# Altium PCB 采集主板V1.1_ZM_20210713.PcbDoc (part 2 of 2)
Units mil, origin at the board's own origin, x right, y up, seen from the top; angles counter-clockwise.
Board outline 5118.11 x 2559.06 mil, 4 copper layers (Top Layer, GND, Power, Bottom Layer), stack 30.635 mil thick; 191 components, 119 nets, 558 pads, 477 vias.
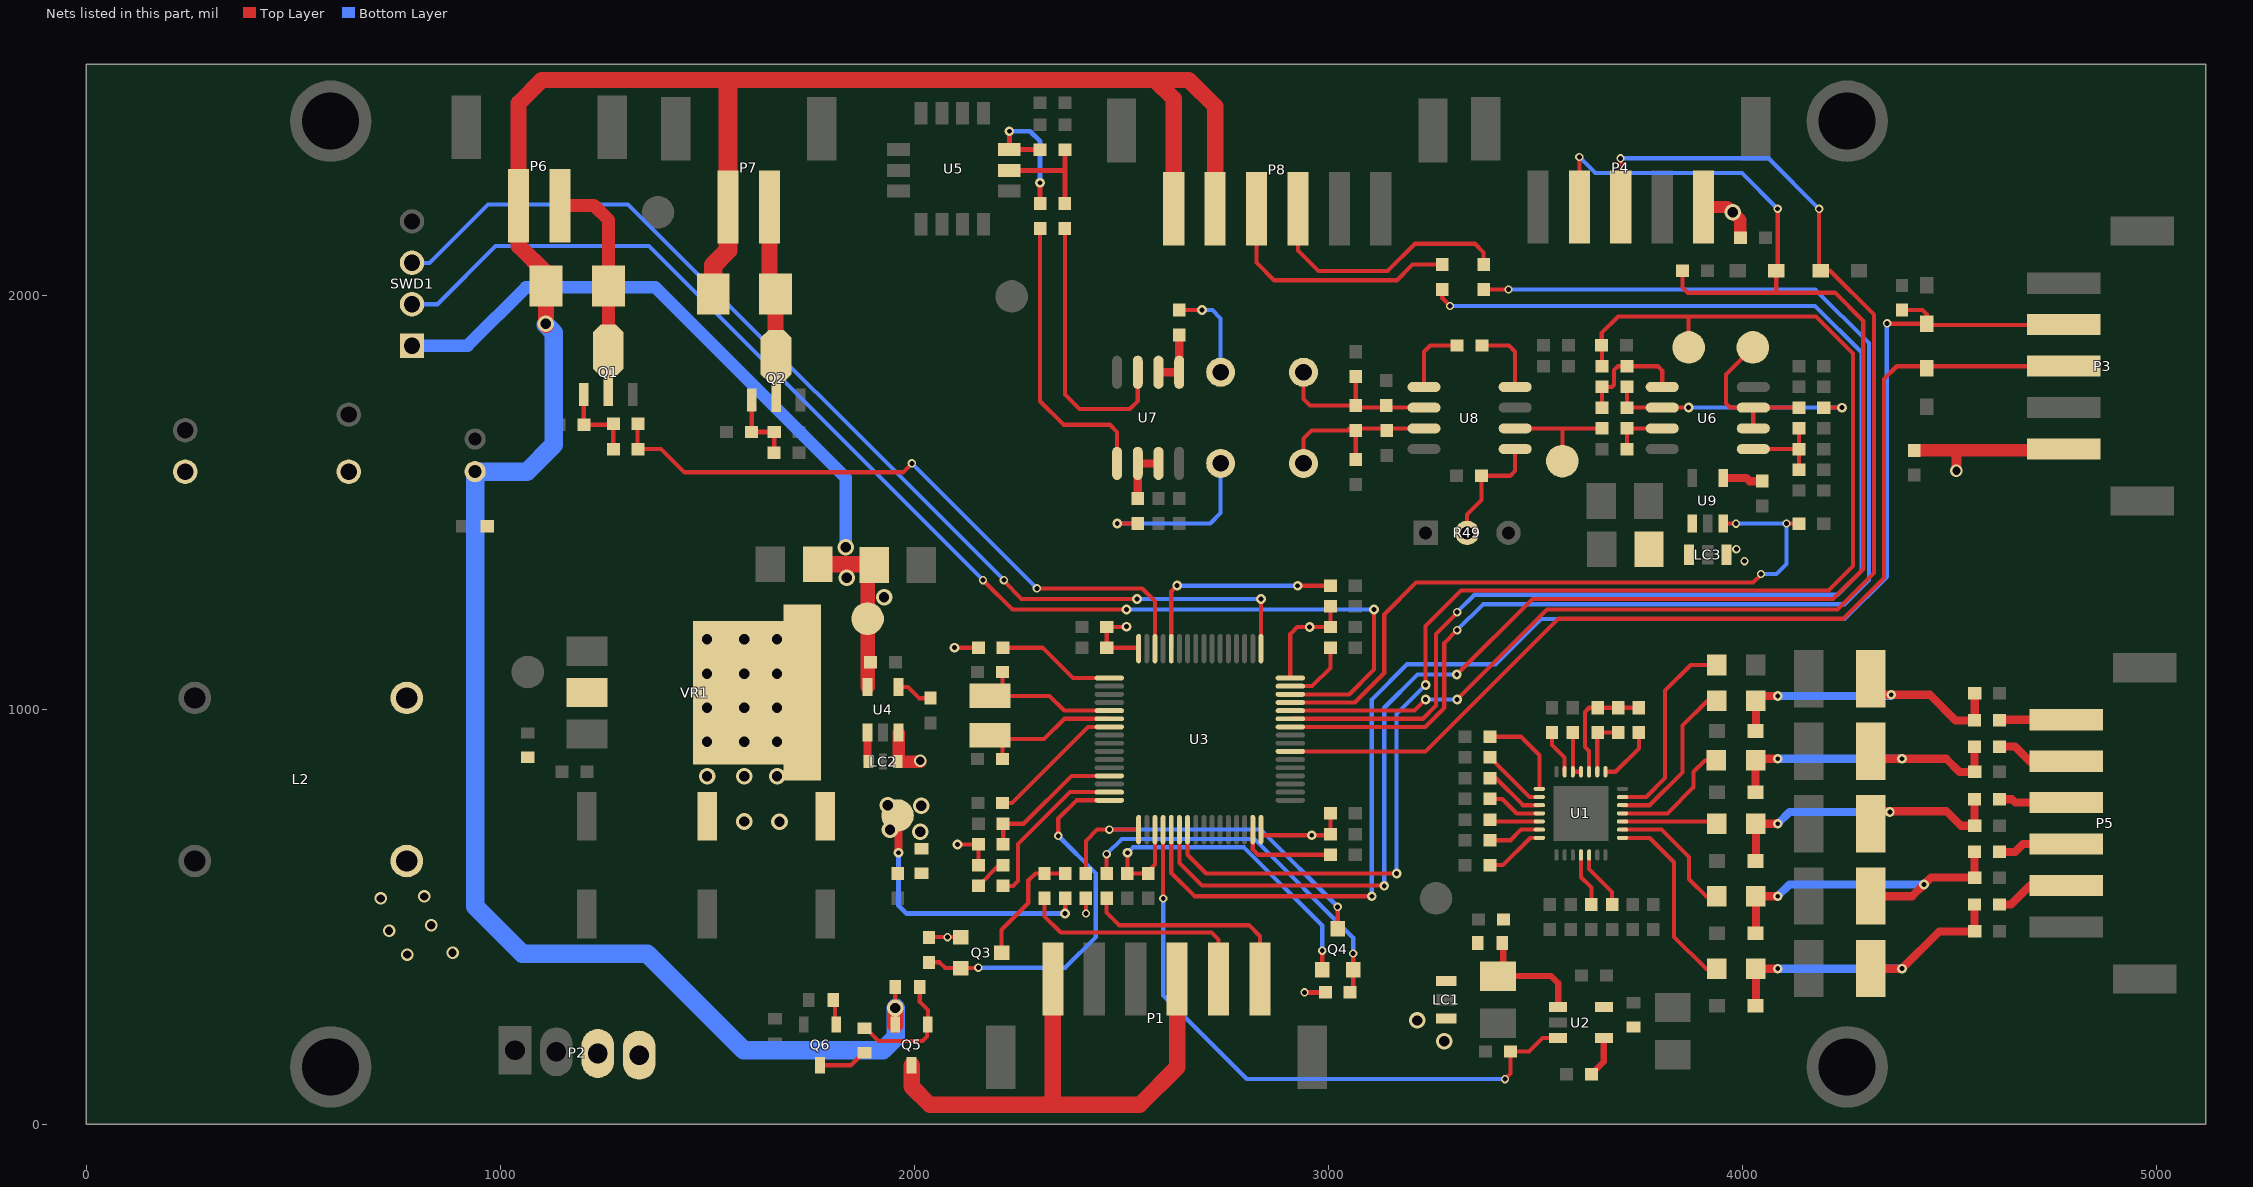
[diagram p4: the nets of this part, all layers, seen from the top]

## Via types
v1: diameter 30, hole 20, Top Layer to Bottom Layer, tented both sides, 321 vias
v2: diameter 40, hole 25, Top Layer to Bottom Layer, tented both sides, 61 vias
v3: diameter 23.62, hole 11.81, Top Layer to Bottom Layer, tented both sides, 49 vias
v4: diameter 20, hole 12, Top Layer to Bottom Layer, tented both sides, 45 vias
v5: diameter 20, hole 12, Top Layer to Bottom Layer, 1 vias

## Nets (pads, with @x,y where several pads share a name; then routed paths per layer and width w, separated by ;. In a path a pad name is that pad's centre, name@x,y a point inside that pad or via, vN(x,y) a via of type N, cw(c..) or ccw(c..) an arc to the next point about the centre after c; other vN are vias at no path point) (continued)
NetC3_1: C3.1 C4.1 C5.2 FB3.1 VR1.2 | length 2.7
  Top Layer w39.37: C4.1@1784.25,743.11 C4.1@1786.14,745
  other v2: 1589.25,730.32 1674.25,730 1499.25,840 1589.25,840 1668.31,840 1499.25,922.5 1589.25,922.5 1668.31,922.5 1499.25,1005 1589.25,1005 1668.31,1005 1499.25,1087.5 1589.25,1087.5 1668.31,1087.5 1499.25,1170 1589.25,1170 1668.31,1170
NetC6_2: C6.2 U1.26 | length 142.5
  Top Layer w10: U1.26@3628.94,649.61 3628.94,615.32 3684.25,560 C6.2@3684.25,530
NetC7_1: C7.1 R22.1 U1.9 | length 144
  Top Layer w10: U1.9@3648.62,850.39 C7.1@3648.62,944.37 ; C7.1@3649.25,945 R22.1@3699.25,945
NetC7_2: C7.2 R20.2 R22.2 U1.10 | length 282.8
  Top Layer w10: U1.10@3628.94,850.39 3628.94,900.32 3619.25,910 3619.25,995 3629.25,1005 C7.2@3649.25,1005 R22.2@3699.25,1005 R20.2@3749.25,1005
NetC8_2: C8.2 U1.11 U1.12 | length 114.4
  Top Layer w10: C8.2@3589.25,945 3589.57,944.68 U1.12@3589.57,850.39 U1.11@3609.25,850.39
NetC13_1: C13.1 C66.1 FB1.2 U2.1 | length 301.9
  Top Layer w15: FB1.2@3421.78,444.17 3421.78,369.61 C13.1@3409.25,357.09 3537.17,357.09 3554.13,340.12 U2.1@3554.13,282.4
NetC16_1: C16.1 Q1.1 R27.1 R29.1 | length 206.4
  Top Layer w10: Q1.1@1201.65,1761.48 R29.1@1201.65,1688.43 1270.63,1688.43 R27.1@1272.87,1690.68 C16.1@1272.87,1629.53
NetC17_1: C17.1 Q2.1 R28.1 R30.1 | length 183
  Top Layer w11.81: Q2.1@1607.06,1747.75 1607.06,1671.67 R30.1@1606.11,1670.73 R28.1@1661.5,1670.73 1661.5,1621.12 C17.1@1661.11,1620.73
NetC20_2: C20.2 U3.31 | length 240.7
  Top Layer w10: U3.31@2816.93,710.63 2816.93,662.32 2829.25,650 C20.2@3004.25,650
NetC21_2: C21.2 U3.47 | length 163.9
  Top Layer w10: U3.47@2907.48,1057.09 2960.24,1057.09 3004.25,1101.1 C21.2@3004.25,1150
NetC22_2: C22.2 L1.1 U3.13 | length 354.1
  Top Layer w10: L1.1@2214.25,675 C22.2@2214.25,725 2263.31,725 2378.86,840.55 U3.13@2470.47,840.55
NetC23_1: C23.1 U3.7 | length 333.5
  Top Layer w10: C23.1@2213.07,775 2235.22,775 2418.88,958.66 U3.7@2470.47,958.66
NetC35_2: C35.2 C39.1 C40.1 R36.1 U8.2 | length 427.5
  Top Layer w10: C35.2@2939.25,1815 2939.25,1750 2954.72,1734.53 C40.1@3065.35,1734.53 C39.1@3065.35,1804.53 ; C40.1@3070.35,1729.53 U8.2@3230.35,1729.53
NetC36_1: C36.1 R35.1 R43.2 U6.2 | length 611.9
  Top Layer w10: C36.1@3720.35,1779.53 R35.1@3720.35,1729.53 U6.2@3805.35,1729.53 v3@3868.78,1729.53 ; R43.2@4195.35,1729.53 v3(4239.25,1729.53)
  Bottom Layer w10: v3(3869.25,1730) v3@4238.78,1730
NetC36_2: C36.2 R35.2 R38.1 U6.1 | length 280
  Top Layer w10: R35.2@3660.35,1729.53 C36.2@3660.35,1779.53 3683.78,1779.53 3689.25,1785 3689.25,1820 3698.78,1829.53 R38.1@3720.35,1829.53 3794.72,1829.53 3805.35,1818.9 U6.1@3805.35,1779.53
NetC40_2: C40.2 C44.2 C48.1 R42.2 U8.3 | length 444.8
  Top Layer w10: C48.1@2939.25,1595 2939.25,1655 2958.78,1674.53 C40.2@3065.35,1674.53 C44.2@3065.35,1604.53 ; 3049.72,1679.53 U8.3@3230.35,1679.53
NetC41_1: C41.1 R41.2 U5.14 | length 353.1
  Top Layer w11.81: v3(2229.04,2396.76) U5.14@2229.04,2352.43 C41.1@2303.37,2352.43 ; R41.2@2303.37,2222.43 v3(2303.37,2272.43)
  Bottom Layer w11.81: v3(2229.04,2396.76) 2279.04,2396.76 2303.37,2372.43 v3(2303.37,2272.43)
NetC41_2: C41.2 R37.2 U5.13 | length 264.3
  Top Layer w11.81: U5.13@2229.04,2302.43 2363.37,2302.43 ; R37.2@2363.37,2222.43 2363.37,2302.43 ; C41.2@2363.37,2352.43 2363.37,2302.43
NetC42_2: C42.2 R39.2 U6.3 | length 135
  Top Layer w10: C42.2@3720.35,1629.53 R39.2@3720.35,1679.53 U6.3@3805.35,1679.53
NetC43_1: C43.1 R38.2 TP7.1 U3.23 | length 3630.9
  Top Layer w10: U3.23@2659.45,710.63 2659.45,649.99 2704.44,605 v3(3164.25,605) ; v3(3234.25,1060) 3234.25,1202.44 3319.68,1287.87 4207.37,1287.87 4266.38,1346.88 4266.38,1859.91 4176.29,1950 3869.25,1950 ; C43.1@3659.25,1880 3659.25,1910 3699.25,1950 3869.25,1950 ; R38.2@3660.35,1829.53 C43.1@3660.35,1878.9 ; TP7.1@3869.25,1875 3869.25,1950
  Bottom Layer w10: v3(3164.25,605) 3164.25,990 v3(3234.25,1060)
NetC45_2: C45.2 R49.2 U8.5 | length 291
  Top Layer w10: R49.2@3334.25,1427.17 3334.25,1471.75 3369.25,1506.75 C45.2@3369.25,1565 3438.43,1565 3450.35,1576.93 U8.5@3450.35,1629.53
NetC49_2: C49.2 R44.2 R45.2 U6.5 | length 210
  Top Layer w10: U6.5@4025.35,1629.53 R45.2@4135.35,1629.53 ; R44.2@4135.35,1579.53 R45.2@4135.35,1629.53 ; C49.2@4135.35,1679.53 R45.2@4135.35,1629.53
NetC50_1: C50.1 LC3.1 U9.1
NetC57_2: C57.2 U2.4 | length 100.1
  Top Layer w15: C57.2@3634.25,120 3664.37,150.12 U2.4@3664.37,207.6
NetC64_2: C64.2 U9.4 | length 97.4
  Top Layer w20: U9.4@3952.76,1559.65 4008.44,1559.65 4016.05,1552.03 C64.2@4047.04,1552.03
NetC65_2: C65.2 U4.4 | length 88.3
  Top Layer w10: U4.4@1961.65,1055.12 1983.95,1055.12 2011.04,1028.03 C65.2@2038.69,1028.03
NetC67_2: C67.2 DS5.1 R17.1 R25.2 TVS9.2 | length 746.6
  Top Layer w19.68: TVS9.2@4031.5,956.5 R17.1@4031.5,1021.65 4031.5,1029.53 4035.63,1033.66 v3(4084.25,1033.66) ; DS5.1@4307.09,1033.66 4325.61,1033.66 4328.4,1036.45 v3(4358.46,1036.45) 4451.65,1036.45 4513.55,974.56 R25.2@4559.55,974.56 4560,975.01 C67.2@4560,1040
  Bottom Layer w19.68: v3(4084.25,1033.66) v3@4358.46,1033.66
NetC68_2: C68.2 DS4.1 R16.1 R47.2 TVS8.2 | length 759.2
  Top Layer w19.68: TVS8.2@4030.71,801.18 R16.1@4030.71,877.95 4030.71,881.1 4031.5,881.89 v3(4084.25,881.89) ; DS4.1@4309.06,881.89 v3(4384.25,881.89) 4491.17,881.89 4523.06,850 C68.2@4560,850 4559.55,850.45 R47.2@4559.55,911.05
  Bottom Layer w19.68: v3(4084.25,881.89) v3(4384.25,881.89)
NetC69_2: C69.2 DS3.1 R15.1 R51.2 TVS7.2 | length 766.5
  Top Layer w19.68: TVS7.2@4031.5,635.79 R15.1@4031.5,725 v3(4084.25,725) ; DS3.1@4309.06,725 4339.06,755 4492.08,755 4527.08,720 C69.2@4560,720 4559.55,720.45 R51.2@4559.55,784.03
  Bottom Layer w19.68: v3(4084.25,725) 4112.63,753.38 v3(4354.97,753.38)
NetC70_2: C70.2 DS2.1 R13.1 R52.2 TVS6.2 | length 838.8
  Top Layer w19.68: TVS6.2@4031.5,460.79 R13.1@4031.5,550 v3(4084.25,550) ; DS2.1@4309.06,550 4409.1,550 v3(4437.53,578.42) 4454.1,595 C70.2@4560,595 4559.55,595.45 R52.2@4559.55,657.02
  Bottom Layer w19.68: v3(4084.25,550) 4112.68,578.42 v3(4437.53,578.42)
NetC71_2: C71.2 DS1.1 R11.1 R53.2 TVS5.2 | length 795.4
  Top Layer w19.68: TVS5.2@4031.5,285.79 R11.1@4031.5,375 v3(4084.25,375) ; DS1.1@4309.06,375 v3(4384.25,375) 4474.25,465 C71.2@4560,465 4559.55,465.45 R53.2@4559.55,530.01
  Bottom Layer w19.68: v3(4084.25,375) v3(4384.25,375)
NetD1_1: D1.1 P6.2 Q1.2 | length 446.5
  Top Layer w31.5: P6.2@1144.24,2217.35 1226.64,2217.35 1261.19,2182.8 D1.1@1261.19,2023.52 1261.19,1868.27 Q1.2@1260.7,1867.78
NetD2_1: D2.1 P7.2 Q2.2 | length 443.2
  Top Layer w31.5: Q2.2@1666.11,1818.61 Q2.2@1666.11,1854.04
  Top Layer w39.37: P7.2@1649.97,2214 1649.97,2018.62 D2.1@1664.65,2003.94 1664.65,1820.08 Q2.2@1666.11,1818.61 ; Q2.2@1666.11,1854.04 Q2.2@1670.16,1858.1
NetFB1_1: FB1.1 LC1.1
NetFB2_1: FB2.1 U2.5
NetLC2_1: LC2.1 U4.1 | length 70.7
  Top Layer w19.68: U4.1@1886.85,944.88 1886.85,876.97 LC2.1@1888.82,875
NetLED1_1: LED1.1 R26.2 | length 80.7
  Top Layer w10: LED1.1@2154.25,575 2204.25,625 R26.2@2214.25,625
NetLED1_2: LED1.2 U3.15 | length 402.1
  Top Layer w10: LED1.2@2214.25,575 2238.39,575 2250.43,587.04 2250.43,676.18 2375.43,801.18 U3.15@2470.47,801.18
NetP3_2: P3.2 R5.2 TVS1.2 U3.21 | length 3576.9
  Top Layer w10: U3.21@2620.08,710.63 2620.08,606.26 2676.34,550 v3(3104.25,550) ; v4(4348.44,1933.23) 4349.58,1932.09 TVS1.2@4444.25,1932.09 4444.25,1954.95 4434.21,1965 R5.2@4384.25,1965 ; TVS1.2@4444.25,1929.53 4774.53,1929.53 P3.2@4775,1930
  Bottom Layer w10: v3(3104.25,550) 3104.25,1025 3189.25,1110 3402.7,1110 3512.18,1219.49 4245.8,1219.49 4347.58,1321.27 v4@4347.58,1931.06
NetP3_3: P3.3 TVS4.2 U3.39 | length 2534.4
  Top Layer w10: U3.39@2907.48,899.61 3234.25,899.61 3554.65,1220 4242.63,1220 4341.11,1318.48 4341.11,1799.02 4371.63,1829.53 4774.53,1829.53 P3.3@4775,1830
NetP4_2: P4.2 R6.2 TVS2.2 U3.22 | length 4281.4
  Top Layer w10: U3.22@2639.76,710.63 2639.76,630.28 2694.25,575.79 v3@3134.25,575.79 ; v3(3309.25,1085) 3491.97,1267.72 4218.02,1267.72 4290.74,1340.44 4290.74,1938.51 4222.13,2007.13 4080.71,2007.13 ; P4.2@3605.35,2214 v4(3605.35,2334.53) ; R6.2@3854.25,2060 3854.25,2019.76 3866.89,2007.13 4080.71,2007.13 ; TVS2.2@4080.71,2060 4080.71,2007.13 ; TVS2.2@4084.25,2063.54 v4@4084.25,2209.53
  Bottom Layer w10: v3(3134.25,575) 3134.25,1005 3214.25,1085 v3(3309.25,1085) ; v4(3605.35,2334.53) 3643.83,2296.06 3997.72,2296.06 v4(4084.04,2209.74) v4@4084.25,2209.53
NetP4_3: P4.3 TVS3.2 U3.44 | length 3138.4
  Top Layer w10: U3.44@2907.48,998.03 3207.28,998.03 v3(3234.25,1025) ; v3(3310.35,1025) 3527.48,1242.13 4228.44,1242.13 4316.68,1330.36 4316.68,1953.95 4210.63,2060 TVS3.2@4187.8,2060 ; P4.3@3705.35,2214 v4@3705.35,2332.76 ; TVS3.2@4184.25,2063.54 v4(4184.25,2209.53)
  Bottom Layer w10: v3(3234.25,1025) v3(3310.35,1025) ; v4(3704.45,2331.63) 4062.15,2331.63 v4(4184.25,2209.53)
NetP5_1: P5.1 R25.1 | length 162.1
  Top Layer w19.68: R25.1@4619.55,974.56 4620.98,975.98 P5.1@4781.02,975.98
NetP5_2: P5.2 R47.1 | length 176
  Top Layer w19.68: R47.1@4619.55,911.05 4656.84,911.05 4691.91,875.98 P5.2@4781.02,875.98
NetP5_3: P5.3 R51.1 | length 164.8
  Top Layer w19.68: R51.1@4619.55,784.03 4649.67,784.03 4657.72,775.98 P5.3@4781.02,775.98
NetP5_4: P5.4 R52.1 | length 169.3
  Top Layer w19.68: R52.1@4619.55,657.02 4657.58,657.02 4676.54,675.98 P5.4@4781.02,675.98
NetP5_5: P5.5 R53.1 | length 180.5
  Top Layer w19.68: R53.1@4619.55,530.01 4647.38,530.01 4693.36,575.98 P5.5@4781.02,575.98
NetP8_3: P8.3 R33.1 | length 611.7
  Top Layer w10: P8.3@2825.88,2209.74 2825.88,2079.76 2868.58,2037.06 3164.78,2037.06 3202.72,2075 R33.1@3274.25,2075
NetP8_4: P8.4 R34.1 | length 630.5
  Top Layer w10: P8.4@2925.88,2209.74 2925.88,2108.79 2975.17,2059.5 3142.34,2059.5 3208.12,2125.28 3353.36,2125.28 3374.25,2104.38 R34.1@3374.25,2079.53
NetQ3_2: Q3.2 R54.1 U3.16 | length 904.8
  Top Layer w10: R54.1@2035.21,390.39 2060.48,390.39 2074.5,376.38 Q3.2@2111.81,376.38 2153.23,376.38 v4(2154.22,377.37) ; v4(2347.18,695.9) 2347.18,737.43 2391.24,781.5 U3.16@2470.47,781.5
  Bottom Layer w10: v4(2154.22,377.37) 2364.13,377.37 2437.86,451.09 2437.86,605.23 v4(2347.18,695.9)
NetQ3_3: Q3.3 R3.2 R4.1 | length 301.5
  Top Layer w10: Q3.3@2210.24,413.78 2210.24,469.08 2274.7,533.54 2274.7,587.76 2291.94,605 R3.2@2314.06,605 R4.1@2364.06,605 R4.1@2367.13,608.07
NetQ4_2: Q4.2 R1.2 R2.2 | length 890.7
  Top Layer w10: R2.2@2464.06,605 v4(2464.06,651.56) ; R1.2@3051.96,317.76 3059.36,325.16 Q4.2@3059.36,372.69 v4(3059.36,411.78)
  Bottom Layer w10: v4(2464.06,651.56) 2500.61,688.12 2820.8,688.12 3059.36,449.55 v4(3059.36,411.78)
NetQ4_3: Q4.3 R55.2 U3.17 | length 899.1
  Top Layer w10: R55.2@2414.06,605 2414.06,683.62 2441.06,710.63 v4(2470.47,710.63) U3.17@2541.34,710.63 ; Q4.3@3021.96,471.12 v4(3021.96,524.49)
  Bottom Layer w10: v4(2470.47,710.63) 2835.82,710.63 v4(3021.96,524.49)
NetQ5_1: Q5.1 R56.1 R57.2 | length 296.6
  Top Layer w10: R57.2@1879.82,231.03 1882.78,231.03 1913.58,200.23 2019.34,200.23 2030.32,211.2 2030.32,238.23 Q5.1@2032.38,240.29 2032.38,275.46 2012.95,294.89 R56.1@2012.95,331.12
NetQ6_1: Q6.1 R58.1 | length 61.7
  Top Layer w10: R58.1@1804.25,299.01 1807.85,295.4 1807.85,243.85 Q6.1@1811.46,240.25
NetQ6_3: Q6.3 R57.1 | length 120.2
  Top Layer w10: Q6.3@1772.09,141.82 1846.72,141.82 1876.87,171.97 R57.1@1879.82,171.97
NetR7_2: R7.2 U1.20 | length 130.2
  Top Layer w10: R7.2@3389.25,685 3439.25,685 3464.88,710.63 U1.20@3508.86,710.63
NetR8_2: R8.2 U1.19 | length 121.5
  Top Layer w10: R8.2@3389.25,735 3393.94,730.32 U1.19@3508.86,730.32
NetR9_2: R9.2 U1.18 | length 134.1
  Top Layer w10: R9.2@3389.25,785 3419.25,785 3454.25,750 U1.18@3508.86,750
NetR10_2: R10.2 U1.17 | length 146.7
  Top Layer w10: R10.2@3389.25,835 3403.5,835 3468.82,769.68 U1.17@3508.86,769.68
NetR11_2: R11.2 U1.1 | length 463.7
  Top Layer w10: U1.1@3709.65,690.94 3775.24,690.94 3834.25,631.93 3834.25,451.82 3911.07,375 R11.2@3937.01,375
NetR12_2: R12.2 U1.16 | length 159.2
  Top Layer w10: R12.2@3389.25,885 3484.88,789.37 U1.16@3508.86,789.37
NetR13_2: R13.2 U1.2 | length 325.2
  Top Layer w10: U1.2@3709.65,710.63 3804.09,710.63 3870.35,644.37 3870.35,590.97 3911.32,550 R13.2@3937.01,550
NetR14_2: R14.2 U1.15 | length 219.4
  Top Layer w10: R14.2@3389.25,935 3464.13,935 3508.86,890.28 U1.15@3508.86,809.06
NetR15_2: R15.2 U1.3 | length 222
  Top Layer w10: U1.3@3709.65,730.32 R15.2@3931.69,730.32
NetR16_2: R16.2 U1.4 | length 302.2
  Top Layer w10: U1.4@3709.65,750 3818.17,750 3881.34,813.18 3881.34,850.39 3908.9,877.95 R16.2@3936.22,877.95 ; R16.2@3936.22,881.89 R16.2@3937.01,881.89
NetR17_2: R17.2 U1.5 | length 398
  Top Layer w10: U1.5@3709.65,769.68 3775.36,769.68 3854.25,848.58 3854.25,961.71 3914.2,1021.65 R17.2@3937.01,1021.65
NetR18_2: R18.2 U1.21 | length 146.9
  Top Layer w10: R18.2@3389.25,625 3420.75,625 3486.69,690.94 U1.21@3508.86,690.94
NetR19_2: R19.2 U1.6 | length 483.3
  Top Layer w10: U1.6@3709.65,789.37 3766.91,789.37 3812.54,835 3812.54,1046.46 3874.35,1108.27 R19.2@3937.01,1108.27
NetR20_1: R20.1 U1.8 | length 142.5
  Top Layer w10: U1.8@3668.31,850.39 3692.87,850.39 3749.25,906.77 R20.1@3749.25,945
NetR21_2: R21.2 U1.13 | length 107.3
  Top Layer w10: R21.2@3539.25,945 3539.25,915 3569.88,884.37 U1.13@3569.88,850.39
NetR23_2: R23.2 U1.25 | length 130
  Top Layer w10: U1.25@3609.25,649.61 3609.25,595.79 3634.25,570.79 R23.2@3634.25,530
NetR24_1: R24.1 U2.3 U3.20 | length 1510
  Top Layer w10: v4@2600.39,544.68 U3.20@2600.39,710.63 ; v4(3426.02,108.37) 3439.25,121.6 R24.1@3439.25,175 3483.86,175 3516.46,207.6 U2.3@3554.13,207.6
  Bottom Layer w10: v4(2600.67,544.68) 2600.67,310.03 2802.32,108.37 v4(3426.02,108.37)
NetR31_2: R31.2 U3.1 | length 286.6
  Top Layer w10: R31.2@2214.25,1150 2309.25,1150 2382.48,1076.77 U3.1@2470.47,1076.77
NetR32_1: R32.1 U3.60 | length 528.7
  Top Layer w10: U3.60@2620.08,1147.64 2620.08,1285.83 v3(2634.25,1300) ; v3(2925.25,1299.49) 3003.74,1299.49 R32.1@3004.25,1300
  Bottom Layer w10: v3(2634.25,1300) 2634.76,1299.49 v3(2925.25,1299.49)
NetR37_1: R37.1 U7.3 | length 669.2
  Top Layer w10: R37.1@2363.37,2162.43 2363.37,1761.17 2398.45,1726.1 2519.84,1726.1 2539.25,1745.51 U7.3@2539.25,1815
NetR39_1: R39.1 TP6.1 U8.6 | length 289.9
  Top Layer w10: U8.6@3450.35,1679.53 3566.06,1679.53 ; TP6.1@3564.25,1600.39 3564.25,1677.72 3566.06,1679.53 ; R39.1@3660.35,1679.53 3566.06,1679.53
NetR40_1: R40.1 U8.1 | length 171.2
  Top Layer w10: U8.1@3230.35,1779.53 3230.35,1864.53 3245.35,1879.53 R40.1@3310.35,1879.53
NetR40_2: R40.2 U8.8 | length 171.2
  Top Layer w10: R40.2@3370.35,1879.53 3435.35,1879.53 3450.35,1864.53 U8.8@3450.35,1779.53
NetR41_1: R41.1 U7.5 | length 709.8
  Top Layer w10: R41.1@2303.37,2162.43 2303.37,1745.03 2359.97,1688.43 2471.55,1688.43 2489.25,1670.73 U7.5@2489.25,1595
NetR43_1: R43.1 TP9.1 U6.6 U6.7 | length 392.4
  Top Layer w10: TP9.1@4024.25,1875 3959.25,1810 3959.25,1740 3969.72,1729.53 U6.7@4025.35,1729.53 ; U6.6@4025.35,1679.53 U6.7@4025.35,1729.53 ; R43.1@4135.35,1729.53 U6.7@4025.35,1729.53
NetR46_1: R46.1 U3.45 U9.3 | length 1699.8
  Top Layer w10: U3.45@2907.48,1017.72 3063.07,1017.72 3134.25,1088.9 3134.25,1230 3211.34,1307.09 4024.58,1307.09 v4@4044.65,1327.16 ; U9.3@3952.76,1449.41 v4@3983.66,1449.41 ; v4@4105.22,1449.53 R46.1@4135.35,1449.53
  Bottom Layer w10: v4(3983.66,1449.53) 4104.75,1449.53 v4(4105.22,1450) 4105.22,1352.08 4081.19,1328.05 v4(4044.12,1328.05)
NetR48_2: R48.2 U7.1 U7.2 | length 140.2
  Top Layer w19.68: U7.2@2589.25,1815 U7.1@2639.25,1815 2639.25,1904.49 R48.2@2639.76,1905
NetR50_2: R50.2 U7.6 U7.7 | length 135
  Top Layer w19.68: R50.2@2539.37,1510 2539.25,1510.12 U7.6@2539.25,1595 U7.7@2589.25,1595
OSC_IN: C26.2 U3.5 Y1.2 | length 347.2
  Top Layer w10: Y1.2@2183.09,1034.32 Y1.2@2182.3,1033.53 2326.15,1033.53 2361.65,998.03 U3.5@2470.47,998.03 ; Y1.2@2212.3,1048.1 C26.2@2212.3,1091.29
OSC_OUT: C34.2 U3.6 Y1.1 | length 364
  Top Layer w10: Y1.1@2182.3,929.66 Y1.1@2212.3,929.66 ; C34.2@2212.3,881.29 Y1.1@2212.3,929.66 ; Y1.1@2212.3,936.92 Y1.1@2212.3,929.66 ; U3.6@2470.47,978.35 2361.85,978.35 2313.16,929.66 Y1.1@2212.3,929.66
RXD: P1.2 R3.1 | length 582.3
  Top Layer w10: R3.1@2314.06,545 2314.06,501.23 2353.16,462.13 2717.13,462.13 2734.25,445 P1.2@2734.25,350
SWCLK: SWD1.3 U3.49 | length 2621.6
  Top Layer w10: v4@2215.73,1310.68 2258.69,1267.72 v3(2537.4,1267.72) ; U3.49@2836.61,1147.64 v3(2836.61,1267.72)
  Bottom Layer w10: SWD1.3@786.92,2079.19 829.5,2079.19 970.31,2220 1308.73,2220 v4(2215.73,1312.99) ; v3(2537.4,1267.72) v3(2836.61,1267.72)
SWDIO: SWD1.2 U3.46 | length 3109
  Top Layer w10: v4@2170.65,1308.07 2236.6,1242.13 v3(2511.81,1242.13) ; U3.46@2907.48,1037.4 3049.72,1037.4 3109.25,1096.93 v3(3109.25,1242.13)
  Bottom Layer w10: SWD1.2@786.92,1979.19 848.06,1979.19 988.86,2120 1358.76,2120 v4(2165.77,1312.99) ; v3(2511.81,1242.13) v3(3109.25,1242.13)
TST+: C48.2 R50.1 | length 429.5
  Top Layer w10: v3(2489.72,1450) R50.1@2539.37,1450
  Bottom Layer w10: v3(2489.72,1450) 2714.25,1450 2739.25,1475 C48.2@2739.25,1595
TST-: C35.1 R48.1 | length 237.8
  Top Layer w10: R48.1@2639.76,1965 v3(2694.25,1965)
  Bottom Layer w10: v3(2694.25,1965) 2719.25,1965 2739.25,1945 C35.1@2739.25,1815
TXD: P1.1 R2.1 | length 531.8
  Top Layer w10: R2.1@2464.06,545 2464.06,510.28 2494.33,480 2807.56,480 2834.25,453.31 P1.1@2834.25,350
US1_RX: R33.2 U3.43 | length 3243.5
  Top Layer w10: U3.43@2907.48,978.35 3227.6,978.35 3259.25,1010 3259.25,1183.23 v4@3311.11,1235.08 ; R33.2@3274.25,2015 3274.25,1994.09 v4(3293.25,1975.09)
  Bottom Layer w10: v4(3293.25,1975.09) 4174.48,1975.09 4286.29,1863.29 4286.29,1335.67 4228.42,1277.8 3352.32,1277.8 v4(3310.35,1235.83)
US1_TX: R34.2 U3.42 | length 3196.9
  Top Layer w10: U3.42@2907.48,958.66 3233.19,958.66 3277.13,1002.6 3277.13,1002.87 3279.25,1005 3279.25,1161.12 v4(3310.35,1192.22) v4@3314.24,1196.11 ; R34.2@3374.25,2015 v4(3434.25,2015)
  Bottom Layer w10: v4(3310.35,1192.22) 3372.87,1254.74 4245.8,1254.74 4304.54,1313.48 4304.54,1885.22 4174.76,2015 v4(3434.25,2015)
V5.0: C59.2 C63.2 FB3.2 LC1.3 LC2.3 LC3.3 P3.5 P4.5 R1.1 R4.2 TP2.1 U4.3 | length 1386.9
  Top Layer w11.81: v3(2363.37,508.49) 2364.06,509.17 R4.2@2364.06,545 ; v4(2941.83,317.76) R1.1@2991.96,317.76
  Top Layer w19.68: v3(1961.65,655) TP2.1@1961.65,750
  Top Layer w23.62: v1(4515.75,1576.93) 4515.75,1612.2
  Top Layer w30: U4.3@1961.65,944.88 1961.65,876.97 LC2.3@1959.69,875 v1@2014.25,875 ; P4.5@3905.35,2214 3962.61,2214 v2(3975.52,2201.09) 3994.25,2182.35 C59.2@3994.25,2140.07 ; C63.2@4413.71,1626.41 4771.41,1626.41 P3.5@4775,1630
  Bottom Layer w11.81: v3(1961.65,655) 1961.65,527.03 1980.2,508.49 v3(2363.37,508.49)
  other v1: 2014.25,876.97
  other v2: 3279.25,200 3214.25,250 2014.25,705.68 1940.91,710.69 2016.77,768.01 1935.12,769.68
  other v4: 4004.32,1358.94 3984.25,1387.8
V12: C58.2 C60.1 C61.1 C62.1 D1.2 D2.2 FB4.1 L2.2 P6.1 P7.1 P8.1 P8.2 Q5.2 R56.2 | length 6294.5
  Top Layer w10: v2(1953.35,280.07) 1953.62,280.34 1953.62,330.85 R56.2@1953.89,331.12
  Top Layer w39.37: v2@1110.4,1929.53 D1.2@1110.4,2023.52 1110.4,2054.58 1044.24,2120.74 P6.1@1044.24,2217.35 1044.24,2464.68 1100.4,2520.83 2580.24,2520.83 ; P8.1@2625.88,2209.74 2625.88,2475.19 2580.24,2520.83 ; P8.2@2725.88,2209.74 2725.88,2456.89 2661.94,2520.83 2580.24,2520.83
  Top Layer w40: v2(1953.35,280.07) 1953.63,279.78 Q5.2@1953.63,240.29
  Top Layer w45: D2.2@1513.86,2003.94 1513.86,2073.59 1549.97,2109.7 P7.1@1549.97,2214 1549.97,2513.8
  Bottom Layer w45: v2@1110.4,1929.53 1129.36,1910.57 1129.36,1639.8 1064.56,1575 C62.1@939.25,1575 939.25,525.22 1053.48,410.99 1355.08,410.99 1588.17,177.9 1923.29,177.9 1954.7,209.31 v2@1954.7,280.07
  other v2: 1109.86,1932.09
VALUE: C16.2 R27.2 U3.62 | length 1593.1
  Top Layer w10: R27.2@1331.69,1690.68 1331.69,1630.71 C16.2@1332.87,1629.53 1388.5,1629.53 1444.6,1573.43 1972.24,1573.43 v4(1993.82,1595) ; v4@2297,1293.31 2550.08,1293.31 2580.98,1262.41 U3.62@2580.98,1147.64
  Bottom Layer w10: v4(1993.82,1595) v4@2295.62,1293.2
  other v4: 2295.42,1293.39
VCC: C18.2 C19.2 C24.2 C25.1 C27.2 C28.2 C29.2 C30.2 C31.2 C32.2 C33.1 L1.2 Q3.1 Q4.1 R26.1 R31.1 R54.2 R55.1 SWD1.1 TP5.1 U3.19 U3.32 U3.48 U3.64 U4.5 | length 3674.4
  Top Layer w10: C33.1@1766.34,1351.57 C33.1@1771.65,1356.89 ; R54.2@2035.21,450.39 2036,451.18 v4(2079.87,451.18) Q3.1@2111.81,451.18 ; v3@2096.77,1150 v3(2096.85,1150) R31.1@2154.25,1150 ; v3(2104.25,675) L1.2@2154.25,675 R26.1@2154.25,625 ; v4(2414.06,508.4) R55.1@2414.06,545 ; v3(2511.81,1200.79) 2511.02,1200 C32.2@2464.25,1200 C27.2@2464.25,1150 2538.98,1150 U3.64@2541.34,1147.64 ; v3(2514.73,655) 2514.25,654.52 C28.2@2514.25,605 2559.06,605 2580.71,626.65 U3.19@2580.71,710.63 ; U3.32@2838.23,697.2 v3(2959.25,697.2) C30.2@2998.03,697.2 ; U3.48@2909.25,1078.54 U3.48@2907.48,1076.77 2907.48,1183.23 2924.25,1200 v3(2954.25,1200) C18.2@3004.25,1200 C19.2@3004.25,1250 ; Q4.1@2984.56,372.69 v4(2984.56,418.54) ; C30.2@3004.25,700 C31.2@3004.25,750
  Top Layer w35: U4.5@1886.85,1055.12 TP5.1@1886.85,1220 C25.1@1886.85,1347.6
  Top Layer w40: C33.1@1766.34,1351.57 1882.87,1351.57 C25.1@1886.85,1347.6
  Bottom Layer w10: v3(2514.73,655) 2527.74,668.01 2795.51,668.01 2984.56,478.96 v4(2984.56,418.54)
  Bottom Layer w30: SWD1.1@786.92,1879.19 921.11,1879.19 1061.91,2020 1374.37,2020 1834.25,1560.12 v2(1834.25,1392.87)
  other v2: 1926.6,1272.09 1836.92,1319.15
VCC_BP: P1.3 P1.6 Q5.3 | length 1271.9
  Top Layer w40: Q5.3@1993,141.87 1993,90.21 2036.78,46.43 2318.41,46.43 ; P1.6@2334.25,350 2334.25,62.27 2318.41,46.43 ; P1.3@2634.25,350 2634.25,136.55 2544.13,46.43 2318.41,46.43
VCC_IN: L2.1 P2.3 P2.4
  other v1: 775.23,409.04 884.83,413.42 731.53,466.5 833.18,479.98 711.41,544.68 816.58,549.48
pads on no net: U1.7 U1.23 U1.24 U3.2 U3.3 U3.4 U3.8 U3.9 U3.10 U3.11 U3.14 U3.24 U3.25 U3.27 U3.28 U3.29 U3.30 U3.40 U3.50 U3.56 U3.57 U3.58 U3.59 U5.2 U5.10 U5.11

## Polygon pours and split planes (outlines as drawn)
EGND on Power "EGND_L01_P080" (solid, remove dead copper, pour order 90): -209.28,2723.01 -205.39,2719.12 2072.24,2719.12 2072.24,2268.61 2162.21,2268.61 2162.21,2676.37 3846.31,2676.37 3846.31,1415.86 2162.21,1415.86 2162.21,1460.55 1203.66,1460.55 1203.66,-48.25 -73.24,-48.25 -213.16,91.68 -135.43,169.41 -135.43,2734.67
AV3.3 on Power "Top Layer-No Net" (solid, remove dead copper, pour order 58): 2228.64,2473.36 2984.15,2473.29 3041.59,2415.84 3041.59,2195.04 3041.59,2103.48 3077.49,2067.58 3206.74,1938.33 3599.88,1938.33 4203.06,1938.33 4221.01,1920.38 4285.63,1855.75 4285.63,1552.37 4285.63,1430.45 4250.23,1430.45 4190.34,1430.45 3619.63,1430.45 3619.63,1319 3449.09,1319 3314.45,1319 3296.5,1336.95 3294.71,1338.75 3294.71,1444.66 3294.71,1543.39 3276.76,1561.35 3271.37,1555.96 3099.04,1555.96 2238.08,1555.96 2143.48,1650.56 2143.48,2388.2
V5.0 on Power "Top Layer-No Net" (solid, remove dead copper, pour order 96): 1375.8,1345.71 1641.14,1345.64 1674.11,1312.68 1681.6,1305.18 1681.6,1138.84 1681.6,1012.96 1687.59,1006.97 1705.58,988.99 1832.95,988.99 2036.04,988.99 2043.14,981.89 2043.14,372.54 2867.97,372.54 3086.62,591.18 3086.62,1182.01 3153.43,1248.82 3178.2,1273.59 3334.24,1273.59 3611.27,1273.59 3623.04,1285.36 3623.57,1285.88 3623.57,1345.76 3623.57,1375.17 3643.53,1395.13 3645.63,1397.23 3981.25,1397.23 4290.14,1397.23 4322.54,1429.63 4322.54,1475.46 4322.54,2050.4 3897.54,2050.4 3897.54,2509.59 5238.13,2509.59 5238.13,-135.61 4488.56,-135.61 1542.9,-135.61 1475.44,-68.15 1301.98,105.31 1301.98,204.89 1301.98,1300.08 1343.4,1341.5 1347.61,1345.71
VCC on Power "Top Layer-No Net" (solid, remove dead copper, pour order 56): 1774.62,1420.47 2970.42,1420.46 2984.78,1406.1 3006.97,1383.91 3006.97,1269.05 3006.97,611.17 2984.78,588.98 2809.43,413.63 2060.77,413.63 2060.77,1076.87 1754.04,1076.87 1754.04,1399.88
EVDD on Power "Top Layer-No Net" (solid, remove dead copper, pour order 62): 3371.76,1121.46 3838.67,1121.47 3839.91,1122.7 3916.7,1122.7 3938.99,1100.41 3945.18,1094.22 3945.18,502.22 3945.18,255.77 3916.7,227.28 3823.81,227.28 3361.12,227.28 3334.61,253.79 3334.61,892.35 3334.61,1084.31
EGND on Top Layer "EGND_L01_P080" (solid, remove dead copper, pour order 80): -153.66,2755.56 -149.77,2751.67 2127.87,2751.67 2127.87,2301.16 2217.83,2301.16 2217.83,2708.92 5128.44,2708.92 5147.87,2689.49 5147.87,1515.69 5147.87,1329.12 4051.81,1329.12 2217.83,1329.12 2217.83,1574.96 2127.87,1574.96 2127.87,1235.83 2924.25,1235.83 5175.09,1235.83 5188.99,1221.93 5188.99,-15.69 -17.62,-15.69 -157.54,124.23 -79.81,201.97 -79.81,2767.22
EGND on GND "EGND_L01_P080" (solid, remove dead copper, pour order 88): -153.66,2755.56 -149.77,2751.67 2127.87,2751.67 2127.87,2301.16 2217.83,2301.16 2217.83,2708.92 5128.44,2708.92 5147.87,2689.49 5147.87,1515.69 5147.87,1329.12 4051.81,1329.12 2217.83,1329.12 2217.83,1574.96 2127.87,1574.96 2127.87,1235.83 2924.25,1235.83 5203.47,1235.83 5203.47,-15.69 -17.62,-15.69 -157.54,124.23 -79.81,201.97 -79.81,2767.22
EGND on Bottom Layer "EGND_L01_P080" (solid, remove dead copper, pour order 92): -153.66,2755.56 -149.77,2751.67 2127.87,2751.67 2127.87,2301.16 2217.83,2301.16 2217.83,2708.92 5128.44,2708.92 5147.87,2689.49 5147.87,1515.69 5147.87,1329.12 4051.81,1329.12 2217.83,1329.12 2217.83,1574.96 2127.87,1574.96 2127.87,1235.83 2924.25,1235.83 5413.75,1235.83 5413.75,-15.69 -17.62,-15.69 -157.54,124.23 -79.81,201.97 -79.81,2767.22

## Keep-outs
Keep-Out Layer:
  lines w7.87: 7.94,7.62 5107.25,7.62 5107.25,2552.33 7.94,2552.33 7.94,7.62
Mechanical 1:
  the board outline again, w7.87

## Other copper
Top Layer:
  rectangle net NetC13_1: 3391.79,329.33 3454.66,509.42
  rectangle net NetFB1_1: 3240.74,328.67 3317.71,462.95
  rectangle net NetFB1_1: 3240.74,413.42 3379.25,462.95
  rectangle net V5.0: 3184.87,174.24 3314.25,270
  region net EVDD: 3649.08,386.43 3649.39,386.13 3781.38,386.13 3810.73,415.48 3840.85,415.48 3881.76,374.57 3881.76,246.72 3877.95,242.91 3780.71,242.91 3773.27,250.35 3773.27,266.18 3763.88,275.57 3720.03,275.57 3704.45,291.14 3704.45,313.19 3683.67,333.97 3650.66,333.97 3643.33,341.3 3643.33,380.67 3649.08,386.43
  region net NetFB2_1: 3642.56,297.9 3686.62,297.9 3690.15,294.37 3690.15,280.05 3711.06,259.14 3750.44,259.14 3754.63,254.94 3754.63,216.39 3752.43,214.19 3752.2,214.42 3714.83,214.42 3665.22,264.03 3638.98,264.03 3636.19,266.82 3636.19,294.15 3640.05,298.01 3642.25,298.01
  region net V12: 185.86,1622.59 190.15,1622.59 826.79,1622.59 843.48,1605.9 986.96,1605.9 1015.59,1577.27 1015.59,903.96 1098.75,903.96 1101.72,900.99 1101.72,861.18 1094.28,853.74 814,853.74 690.33,977.41 690.33,1052.57 938.54,1300.78 938.54,1476.9 916.26,1499.18 347.79,1499.18 189.08,1499.18 176.59,1511.68 176.59,1614.53
  region net NetC1_2: 1261.19,978.35 1154.56,978.35 1149.81,973.6 1047.22,973.84 1044.24,970.86 1044.24,915.04 1044.96,914.32 1149.25,914.32 1159.83,903.74 1260.44,903.74 1261.19,902.99
  region net NetC3_1: 1808.48,822.66 1824.76,806.38 1824.76,734.3 1924.06,635 2045.9,635 2054.11,626.79 2054.11,587.43 2046.25,579.57 1862,579.57 1716.04,725.53 1716.04,822.66
  region net V5.0: 1916.05,801.18 2050.63,801.18 2062.65,789.16 2062.65,654.68 2055.7,647.73 1931.52,647.73 1908.27,670.99 1908.27,793.4 1915.4,800.54
  region net VCC_IN: 854.25,752.69 854.25,525 969.25,410 1385.62,410 1425.37,370.25 1425.37,127.1 1383.27,85 1209.25,85 1192.29,101.96 1192.29,261.96 1147.94,306.31 827.94,306.31 659.25,475 659.25,750.82 682.73,774.29 838.83,774.29
  region net NetC3_1: 1164.25,1076.77 1326.02,1076.77 1464.25,1215 1504.25,1215 1504.25,905 1469.25,870 1464.25,870 1329.25,1005 1164.25,1005
  region net NetC3_1: 1766.34,920 1429.25,920 1429.25,700 1454.25,675 1808.31,675 1824.25,690.94 1824.25,806.89 1766.34,864.8
  region net NetC50_1: 3736.49,1433.97 3847.91,1433.97 3860.26,1446.32 3860.26,1473.26 3865.2,1478.19 3887.39,1478.19 3890.6,1474.99 3890.35,1350.93 3879.01,1339.58 3736.68,1339.58 3727.33,1348.94 3727.33,1425.41 3735.88,1433.97
  region net AV3.3: 3734.88,1549.23 3769.35,1583.7 3889.88,1583.7 3893.4,1580.18 3893.4,1535.88 3888.12,1530.6 3839.85,1530.6 3817.4,1508.15 3817.4,1465.92 3807.84,1456.36 3734.85,1456.36 3729.32,1461.89 3729.32,1543.67
  region net V5.0: 3948.97,1399.21 4009.32,1399.36 4014.66,1394.02 4014.66,1352.01 4010.64,1347.99 3949.55,1347.99 3948.97,1348.63
  region net VCC: 1727.69,1417.16 1935.85,1417.16 1954.25,1398.76 1954.25,1190.58 1916.82,1153.15 1916.82,1037.64 1907.88,1028.7 1868.64,1028.7 1864.77,1032.56 1864.77,1148.7 1829.23,1184.24 1829.23,1278.8 1812.1,1295.94 1725.15,1295.94 1715,1306.09 1715,1409.05 1723.09,1417.15 1727.55,1417.15
  region net GND_IN: 27.03,769.68 598.13,769.68 628.13,739.68 628.13,429.28 789.95,267.45 1157.54,267.45 1180.16,244.83 1180.16,49.05 1152.62,21.51 27.03,21.51
Power:
  region net GND_IN: 27.03,769.68 464.1,769.68 522.46,711.32 522.46,534.94 789.95,267.45 1157.54,267.45 1180.16,244.83 1180.16,49.05 1152.62,21.51 27.03,21.51
GND:
  region net GND_IN: 27.03,769.68 464.1,769.68 522.46,711.32 522.46,534.94 789.95,267.45 1157.54,267.45 1180.16,244.83 1180.16,49.05 1152.62,21.51 27.03,21.51
Bottom Layer:
  region net GND_IN: 27.03,769.68 464.1,769.68 522.46,711.32 522.46,534.94 789.95,267.45 1157.54,267.45 1180.16,244.83 1180.16,49.05 1152.62,21.51 27.03,21.51

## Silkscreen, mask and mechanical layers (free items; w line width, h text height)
Top Overlay:
  circle w19.68: c590.55,2421.26 r129.92
  circle w19.68: c4251.97,2421.26 r129.92
  circle w19.68: c4251.97,137.8 r129.92
  circle w19.68: c590.55,137.8 r129.92
  text "心音" at 3984.25,2225.41 h78.74
  text "主机通讯" at 3174.42,2201.86 h78.74
  text "GND" at 588.8,2155.52 h40
  text "SWCLK" at 509.97,2060.93 h40
  text "SWDIO" at 515.23,1962.13 h40
  text "VCC" at 588.8,1878.05 h40
  text "颈动脉波" at 4631.25,1394 h78.74
  text "-" at 997.86,331.66 h78.74
  text "-" at 1108.3,330.72 h78.74
  text "+" at 1227.24,330.72 h78.74
  text "+" at 1357.51,329.78 h78.74
  text "血压计" at 3153.71,67.23 h59.06
  text "HD-XXG-V2.3" at 3749.25,59.53 h59.06
  text "2023-12-26" at 3784.25,9.53 h59.06
Top Solder:
  rectangle: 1169.25,1009.53 1349.25,1089.53
  lines w100: 3104.57,96.19 3106.18,215.77 ; 4460.44,1178.55 4826.08,1178.55 ; 4478.89,235.29 4844.54,235.29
